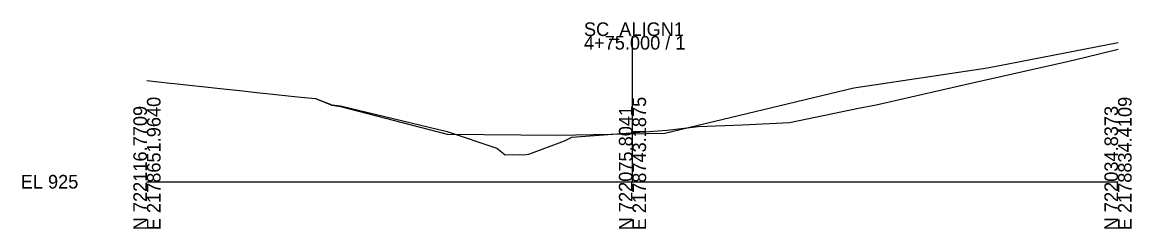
# Model space of a CAD drawing. Extents: x -2342 to 14913, y -10 to 5257.
# Drawn here: x 974.3 to 1202.8, y 4490.3 to 4532.8 of the extents above; entities that cross this region are included whole.
import ezdxf

# ---------------------------------------------------------------- set-up
doc = ezdxf.new("R2010")
doc.units = 0
for name, color, linetype in [('Default', 7, 'Continuous'), ('GK_Cells', 7, 'Continuous'), ('SC_Scratch1', 7, 'Continuous'), ('XS_X_Ground_Line', 7, 'Continuous')]:
    doc.layers.add(name, color=color, linetype=linetype)

msp = doc.modelspace()

# ---------------------------------------------------------------- linework, layer by layer
at = {"layer": 'GK_Cells'}
for p, q in [((1100, 4500), (1100, 4530)), ((1000, 4500), (1100, 4500)), ((1100, 4500), (1200, 4500))]:
    msp.add_line(p, q, dxfattribs=at)
at = {"layer": 'SC_Scratch1'}
msp.add_lwpolyline([(1000, 4520.82), (1004.76, 4520.31), (1005.62, 4520.22), (1007.45, 4520.02), (1012.61, 4519.45), (1015.11, 4519.18), (1019.76, 4518.69), (1022.54, 4518.4), (1024.63, 4518.17), (1031.03, 4517.49), (1034.74, 4517.1), (1038.07, 4515.74), (1039.88, 4515.49), (1061.8, 4509.81), (1084.55, 4509.55), (1106.65, 4510.01), (1145.61, 4519.36), (1173.1, 4523.47), (1200, 4528.68)], dxfattribs=at)
at = {"layer": 'XS_X_Ground_Line'}
msp.add_lwpolyline([(1000, 4520.82), (1004.76, 4520.31), (1005.62, 4520.22), (1007.45, 4520.02), (1012.61, 4519.45), (1015.11, 4519.18), (1019.76, 4518.69), (1022.54, 4518.4), (1024.63, 4518.17), (1031.03, 4517.49), (1034.74, 4517.1), (1038.07, 4515.84), (1039.88, 4515.61), (1061.8, 4510.32), (1072.04, 4506.9), (1073.77, 4505.56), (1076.82, 4505.59), (1077.61, 4505.54), (1078.67, 4505.7), (1086.01, 4508.44), (1087.53, 4509.19), (1107.17, 4510.6), (1113.56, 4511.38), (1122.64, 4511.74), (1132.37, 4512.21), (1146.56, 4515.11), (1150.21, 4515.86), (1169.39, 4520.19), (1189.87, 4524.81), (1193.03, 4525.58), (1200, 4527.31)], dxfattribs=at)

# ---------------------------------------------------------------- texts
at = {"layer": 'Default'}
msp.add_text('-', height=0.0001, dxfattribs=at).set_placement((1000, 4500))
at = {"layer": 'GK_Cells'}
for s, p in [('SC_ALIGN1', (1090, 4530)), ('4+75.000 / 1', (1090, 4527.2)), ('EL 925', (974, 4498.6))]:
    msp.add_text(s, height=2.8, dxfattribs=at).set_placement(p)
for s, p in [('E 2178651.9640', (1002.8, 4490)), ('E 2178743.1875', (1102.8, 4490)), ('E 2178834.4109', (1202.8, 4490)), ('N 722116.7709', (1000, 4490)), ('N 722075.8041', (1100, 4490)), ('N 722034.8373', (1200, 4490))]:
    msp.add_text(s, height=2.8, rotation=90, dxfattribs=at).set_placement(p)
at = {"layer": 'SC_Scratch1'}
msp.add_text('X', height=0.0001, dxfattribs=at).set_placement((1100, 4510.09))

doc.saveas('drawing.dxf')
